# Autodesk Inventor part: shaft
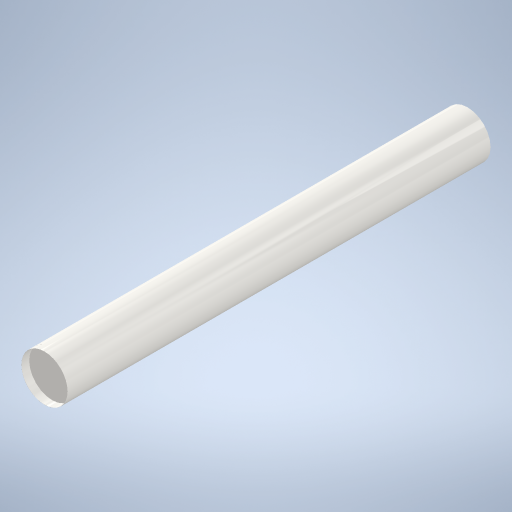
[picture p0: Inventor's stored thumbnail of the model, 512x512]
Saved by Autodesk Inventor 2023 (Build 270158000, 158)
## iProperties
Created: 2023-02
Part Number: shaft
Material: Stal
Document SubType Name: Modeling
Designer: Admin
Density: 7.85 g/cm^3
Appearance: Stal
Mass: 97.6595 g
Surface Area: 43.731 cm^2
Volume: 12.4407 cm^3
Author: Admin
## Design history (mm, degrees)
sketch "Szkic1"
  geometry: C1 r 6 at (0, 0); 1 further point
  constraints: 1 centre point, 1 coincident
  dimensions: "d0" = 12 diameter of C1
extrude "Wyciągnięcie proste1" new body sketch "Szkic1" distance "d1" = 110; taper "d2" = 0 deg
sketch "Szkic2"
  geometry: C1 r 5.975 at (0, 0); 1 further point
  constraints: 1 centre point, 1 coincident
  dimensions: "d3" = 11.95 diameter of C1
extrude "Wyciągnięcie proste2" cut sketch "Szkic2" stored distance "d4" = 2; taper "d5" = 0 deg
sketch "Szkic3"
  geometry: C1 r 5.975 at (0, 0); 1 further point
  constraints: 1 centre point, 1 coincident
  dimensions: "d6" = 11.95 diameter of C1
extrude "Wyciągnięcie proste3" cut sketch "Szkic3" stored distance "d7" = 2; taper "d8" = 0 deg
node "Bryła1"
